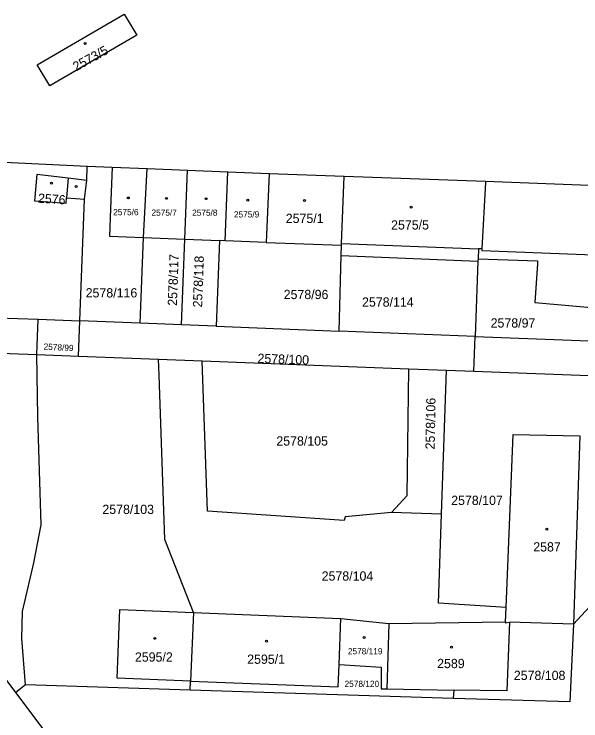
# Model space of a CAD drawing. Extents: x -527335 to -526256, y -1079142 to -1077836.
# Drawn here: x -526804.5 to -526700.3, y -1078355.5 to -1078225.7 of the extents above; entities that cross this region are included whole.
import ezdxf

# ---------------------------------------------------------------- set-up
doc = ezdxf.new("R2010")
doc.units = 0
for name, color, linetype in [('Hranice parcel', 7, 'Continuous'), ('Parcelní čísla', 7, 'Continuous'), ('Vnitřní kresba', 7, 'Continuous'), ('Značky budov', 7, 'Continuous')]:
    doc.layers.add(name, color=color, linetype=linetype)

msp = doc.modelspace()

# ---------------------------------------------------------------- linework, layer by layer
at = {"layer": 'Hranice parcel'}
for p, q in [((-526826.23, -1078251.91), (-526791.08, -1078253.62)), ((-526791.14, -1078256.3), (-526791.08, -1078253.62)), ((-526791.08, -1078253.62), (-526786.5, -1078253.84)), ((-526786.5, -1078253.84), (-526780.07, -1078254.09)), ((-526780.72, -1078266.76), (-526780.07, -1078254.09)), ((-526780.07, -1078254.09), (-526772.64, -1078254.38)), ((-526773.14, -1078267.05), (-526772.64, -1078254.38)), ((-526772.64, -1078254.38), (-526765.2, -1078254.66)), ((-526765.7, -1078267.34), (-526765.2, -1078254.66)), ((-526765.2, -1078254.66), (-526757.63, -1078254.96)), ((-526757.63, -1078254.96), (-526758.15, -1078267.63)), ((-526757.63, -1078254.96), (-526743.82, -1078255.49)), ((-526743.82, -1078255.49), (-526717.88, -1078256.37)), ((-526791.56, -1078259.67), (-526791.14, -1078256.3)), ((-526717.88, -1078256.37), (-526675.26, -1078258.03)), ((-526792.4, -1078282.06), (-526791.56, -1078259.67)), ((-526781.3, -1078282.49), (-526780.72, -1078266.76)), ((-526780.72, -1078266.76), (-526773.14, -1078267.05)), ((-526773.73, -1078282.79), (-526773.14, -1078267.05)), ((-526773.14, -1078267.05), (-526766.73, -1078267.3)), ((-526766.73, -1078267.3), (-526767.38, -1078283.04)), ((-526765.7, -1078267.34), (-526766.73, -1078267.3)), ((-526758.15, -1078267.63), (-526765.7, -1078267.34)), ((-526758.15, -1078267.63), (-526744.34, -1078268.16)), ((-526744.38, -1078270.05), (-526744.34, -1078268.16)), ((-526744.74, -1078283.92), (-526744.38, -1078270.05)), ((-526744.38, -1078270.05), (-526719.25, -1078271.09)), ((-526719.25, -1078271.09), (-526719.79, -1078284.89)), ((-526719.23, -1078270.66), (-526719.25, -1078271.09)), ((-526827.32, -1078280.7), (-526800.05, -1078281.76)), ((-526800.3, -1078288.23), (-526800.05, -1078281.76)), ((-526800.05, -1078281.76), (-526792.4, -1078282.06)), ((-526792.64, -1078288.52), (-526792.4, -1078282.06)), ((-526781.3, -1078282.49), (-526792.4, -1078282.06)), ((-526773.73, -1078282.79), (-526781.3, -1078282.49)), ((-526767.38, -1078283.04), (-526773.73, -1078282.79)), ((-526767.38, -1078283.04), (-526744.74, -1078283.92)), ((-526719.79, -1078284.89), (-526744.74, -1078283.92)), ((-526720.03, -1078291.28), (-526719.79, -1078284.89)), ((-526719.79, -1078284.89), (-526695.92, -1078285.82)), ((-526800.3, -1078288.23), (-526792.64, -1078288.52)), ((-526792.64, -1078288.52), (-526777.97, -1078289.08)), ((-526777.97, -1078289.08), (-526769.95, -1078289.38)), ((-526769.95, -1078289.38), (-526731.94, -1078290.83)), ((-526731.94, -1078290.83), (-526725.04, -1078291.09)), ((-526725.04, -1078291.09), (-526720.03, -1078291.28)), ((-526720.03, -1078291.28), (-526692.39, -1078292.33)), ((-526725.95, -1078317.56), (-526735.11, -1078317.24)), ((-526693.43, -1078328.83), (-526701.71, -1078337.73)), ((-526714.17, -1078337.31), (-526714.07, -1078334.69)), ((-526771.51, -1078335.61), (-526772.06, -1078348.2)), ((-526771.51, -1078335.61), (-526744.43, -1078336.68)), ((-526744.76, -1078345.14), (-526744.43, -1078336.68)), ((-526744.43, -1078336.68), (-526735.62, -1078337.6)), ((-526735.62, -1078337.6), (-526714.17, -1078337.31)), ((-526701.71, -1078337.73), (-526713.46, -1078337.4)), ((-526735.62, -1078337.6), (-526735.98, -1078349.65)), ((-526802.4, -1078348.91), (-526804.2, -1078350.27)), ((-526772.13, -1078349.86), (-526802.4, -1078348.91)), ((-526772.13, -1078349.86), (-526772.06, -1078348.2)), ((-526723.81, -1078351.38), (-526772.13, -1078349.86)), ((-526735.98, -1078349.65), (-526723.71, -1078349.84)), ((-526723.71, -1078349.84), (-526723.81, -1078351.38))]:
    msp.add_line(p, q, dxfattribs=at)
for points in [[(-526797.91, -1078238.86), (-526800.27, -1078235.01), (-526784.26, -1078225.72), (-526781.93, -1078229.6), (-526797.91, -1078238.86)], [(-526786.5, -1078253.84), (-526786.77, -1078261.47), (-526786.95, -1078266.52), (-526780.72, -1078266.76)], [(-526791.14, -1078256.3), (-526794.56, -1078255.87), (-526800.32, -1078255.14), (-526800.76, -1078260.01), (-526794.92, -1078260.41), (-526794.85, -1078259.43), (-526791.56, -1078259.67)], [(-526744.34, -1078268.16), (-526744.32, -1078267.82), (-526743.83, -1078255.55), (-526743.82, -1078255.49)], [(-526717.88, -1078256.37), (-526717.88, -1078256.55), (-526718.54, -1078268.81)], [(-526718.54, -1078268.81), (-526718.55, -1078269.1), (-526675.94, -1078270.75), (-526675.26, -1078258.03)], [(-526718.54, -1078268.81), (-526719.16, -1078268.79), (-526719.23, -1078270.66)], [(-526719.23, -1078270.66), (-526708.29, -1078271.04), (-526708.33, -1078271.55), (-526708.81, -1078278.7), (-526695.63, -1078279.84), (-526695.81, -1078283.53)], [(-526842.74, -1078286.62), (-526817.12, -1078287.6), (-526800.3, -1078288.23)], [(-526804.2, -1078350.27), (-526821.9, -1078326.75), (-526841.53, -1078291.28), (-526842.74, -1078286.62)], [(-526802.4, -1078348.91), (-526803.06, -1078340.39), (-526802.94, -1078335.4), (-526800.87, -1078326.48), (-526799.53, -1078319.5), (-526800.12, -1078299.66), (-526800.3, -1078288.23)], [(-526771.51, -1078335.61), (-526776.79, -1078322.2), (-526777.86, -1078291.99), (-526777.97, -1078289.08)], [(-526735.11, -1078317.24), (-526743.65, -1078318.06), (-526743.85, -1078318.74), (-526768.97, -1078316.99), (-526769.95, -1078289.38)], [(-526735.11, -1078317.24), (-526732.26, -1078314.12), (-526731.94, -1078290.83)], [(-526725.95, -1078317.56), (-526725.21, -1078296.43), (-526725.04, -1078291.09)], [(-526714.07, -1078334.69), (-526712.81, -1078302.9), (-526700.52, -1078303.16), (-526701.71, -1078337.73)], [(-526714.07, -1078334.69), (-526726.53, -1078333.89), (-526725.95, -1078317.56)], [(-526772.06, -1078348.2), (-526785.56, -1078347.68), (-526785.06, -1078335.08), (-526771.51, -1078335.61)], [(-526713.46, -1078337.4), (-526713.93, -1078350), (-526723.71, -1078349.84)], [(-526714.17, -1078337.31), (-526714.24, -1078337.52), (-526713.46, -1078337.4)], [(-526701.71, -1078337.73), (-526702.34, -1078352.03), (-526723.81, -1078351.38)], [(-526772.06, -1078348.2), (-526744.92, -1078349.24), (-526744.76, -1078345.14)], [(-526744.76, -1078345.14), (-526737.02, -1078345.63), (-526737.03, -1078349.63), (-526735.98, -1078349.65)], [(-526761.68, -1078404.12), (-526793.59, -1078364.38), (-526804.2, -1078350.27)]]:
    msp.add_lwpolyline(points, dxfattribs=at)
at = {"layer": 'Vnitřní kresba'}
for p, q in [((-526794.56, -1078255.87), (-526794.85, -1078259.43)), ((-526744.32, -1078267.82), (-526719.16, -1078268.79))]:
    msp.add_line(p, q, dxfattribs=at)
at = {"layer": 'Značky budov'}
for centre in [(-526791.46, -1078231.12), (-526797.6, -1078256.78), (-526793.08, -1078257.38), (-526783.5, -1078259.48), (-526776.48, -1078259.55), (-526769.19, -1078259.61), (-526761.57, -1078259.88), (-526751.11, -1078259.95), (-526731.54, -1078261.17), (-526706.57, -1078320.3), (-526778.64, -1078340.35), (-526758.12, -1078340.89), (-526740.17, -1078340.21), (-526724.11, -1078341.97)]:
    msp.add_circle(centre, 0.175, dxfattribs=at)

# ---------------------------------------------------------------- texts
at = {"layer": 'Parcelní čísla'}
for s, height, rotation, p in [('2573/5', 1.7, 29, (-526793.1, -1078236.25)), ('2576', 1.7, 356, (-526800.15, -1078260.34)), ('2578/117', 1.7, 88, (-526774.57, -1078279.3)), ('2578/118', 1.7, 88, (-526769.95, -1078279.6)), ('2578/99', 1.14, 357, (-526799.1, -1078287.33)), ('2578/100', 1.7, 358, (-526759.79, -1078289.76)), ('2578/106', 1.7, 89, (-526727.21, -1078305.67))]:
    msp.add_text(s, height=height, rotation=rotation, dxfattribs=at).set_placement(p)
for s, height, p in [('2575/6', 1.14, (-526786.28, -1078262.65)), ('2575/7', 1.14, (-526779.25, -1078262.74)), ('2575/8', 1.14, (-526771.78, -1078262.75)), ('2575/9', 1.14, (-526764.1, -1078263.06)), ('2575/1', 1.7, (-526754.57, -1078264.08)), ('2575/5', 1.7, (-526735.21, -1078265.28)), ('2578/116', 1.7, (-526791.34, -1078277.75)), ('2578/96', 1.7, (-526754.95, -1078278.05)), ('2578/114', 1.7, (-526740.55, -1078279.44)), ('2578/97', 1.7, (-526716.92, -1078283.28)), ('2578/105', 1.7, (-526756.3, -1078304.95)), ('2578/107', 1.7, (-526724.17, -1078315.86)), ('2578/103', 1.7, (-526788.27, -1078317.51)), ('2587', 1.7, (-526709.09, -1078324.4)), ('2578/104', 1.7, (-526747.97, -1078329.75)), ('2578/119', 1.139, (-526743.15, -1078343.29)), ('2595/2', 1.7, (-526782.29, -1078344.63)), ('2595/1', 1.7, (-526761.66, -1078345.03)), ('2589', 1.7, (-526726.75, -1078345.82)), ('2578/108', 1.7, (-526712.66, -1078348)), ('2578/120', 1.139, (-526743.76, -1078349.28))]:
    msp.add_text(s, height=height, dxfattribs=at).set_placement(p)

doc.saveas('drawing.dxf')
